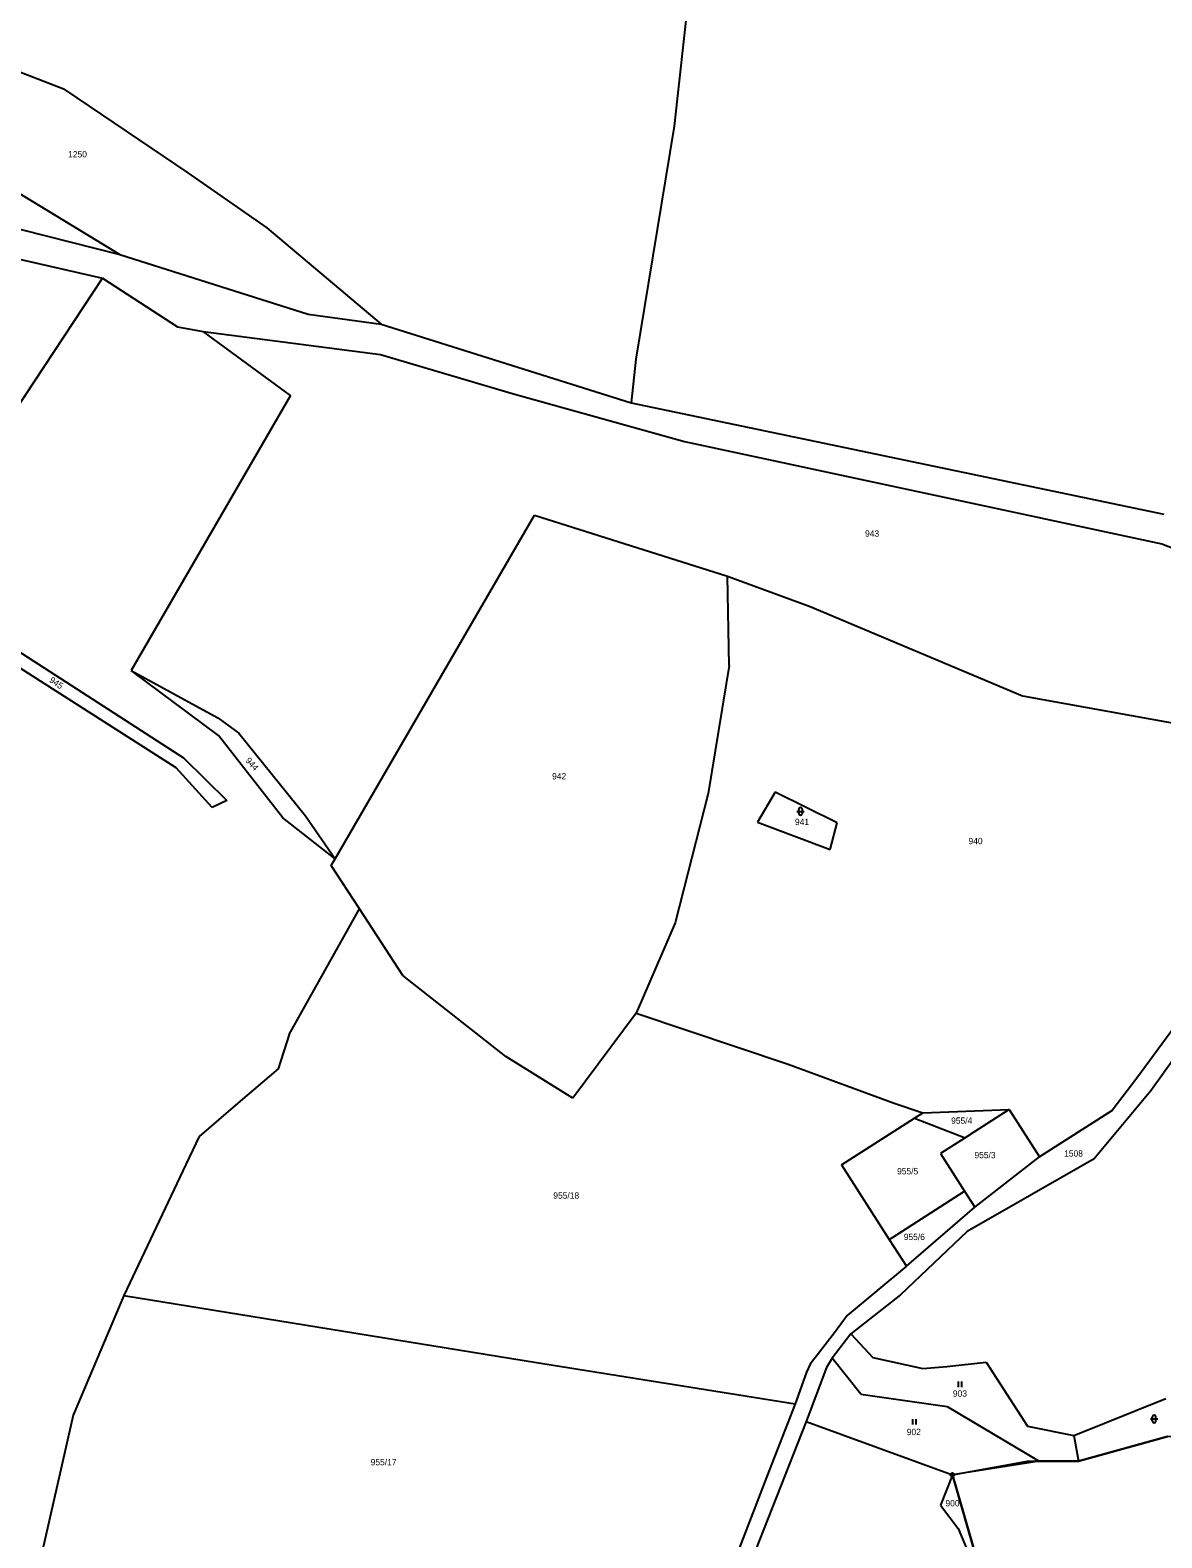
# Model space of a CAD drawing. Extents: x -760642 to -757221, y -1092371 to -1088855.
# Drawn here: x -759517.9 to -759213, y -1091814.5 to -1091408.1 of the extents above; entities that cross this region are included whole.
import ezdxf

# ---------------------------------------------------------------- set-up
doc = ezdxf.new("R2010")
doc.units = 0
for name, color, linetype in [('Vrstva 1', 7, 'Continuous'), ('Vrstva 13', 7, 'Continuous'), ('Vrstva 18', 7, 'Continuous'), ('Vrstva 24', 7, 'Continuous'), ('Vrstva 25', 7, 'Continuous'), ('Vrstva 28', 7, 'Continuous')]:
    doc.layers.add(name, color=color, linetype=linetype)

msp = doc.modelspace()

# ---------------------------------------------------------------- linework, layer by layer
at = {"layer": 'Vrstva 1'}
for p, q in [((-759336.04, -1091359.28), (-759344.44, -1091433.97)), ((-759508.63, -1091424.1), (-759544.7, -1091410.36)), ((-759508.63, -1091424.1), (-759475.4, -1091446.57)), ((-759344.44, -1091433.97), (-759354.76, -1091496.83)), ((-759589.77, -1091444.33), (-759493.77, -1091468.61)), ((-759475.4, -1091446.57), (-759454.15, -1091461.4)), ((-759592.93, -1091453.44), (-759498.45, -1091474.93)), ((-759524, -1091450.19), (-759493.77, -1091468.61)), ((-759454.15, -1091461.4), (-759423.37, -1091487.35)), ((-759493.77, -1091468.61), (-759442.97, -1091484.64)), ((-759551.73, -1091555.78), (-759498.45, -1091474.93)), ((-759498.45, -1091474.93), (-759478.22, -1091488.09)), ((-759442.97, -1091484.64), (-759423.37, -1091487.35)), ((-759478.22, -1091488.09), (-759471.32, -1091489.38)), ((-759447.73, -1091506.59), (-759471.32, -1091489.38)), ((-759471.32, -1091489.38), (-759423.5, -1091495.58)), ((-759423.37, -1091487.35), (-759355.96, -1091508.53)), ((-759423.5, -1091495.58), (-759387.72, -1091506.19)), ((-759354.76, -1091496.83), (-759355.96, -1091508.53)), ((-759387.72, -1091506.19), (-759341.65, -1091518.97)), ((-759447.73, -1091506.59), (-759490.74, -1091580.74)), ((-759355.96, -1091508.53), (-759212.45, -1091538.54)), ((-759341.65, -1091518.97), (-759213.03, -1091546.61)), ((-759435.76, -1091631.5), (-759382, -1091538.82)), ((-759382, -1091538.82), (-759329.99, -1091555.26)), ((-759213.03, -1091546.61), (-759176.04, -1091560.8)), ((-759478.53, -1091606.93), (-759553.56, -1091559.12)), ((-759551.73, -1091555.78), (-759476.57, -1091604.24)), ((-759329.99, -1091555.26), (-759307.72, -1091563.44)), ((-759329.59, -1091579.38), (-759329.99, -1091555.26)), ((-759307.72, -1091563.44), (-759250.54, -1091587.55)), ((-759329.59, -1091579.38), (-759335.2, -1091613.85)), ((-759490.74, -1091580.74), (-759467.33, -1091593.5)), ((-759467.2, -1091598.21), (-759490.74, -1091580.74)), ((-759250.54, -1091587.55), (-759179.64, -1091600.4)), ((-759467.33, -1091593.5), (-759461.7, -1091597.57)), ((-759449.86, -1091620.44), (-759467.2, -1091598.21)), ((-759461.7, -1091597.57), (-759443.7, -1091619.91)), ((-759468.87, -1091617.59), (-759478.53, -1091606.93)), ((-759476.57, -1091604.24), (-759464.95, -1091615.75)), ((-759464.95, -1091615.75), (-759468.87, -1091617.59)), ((-759335.2, -1091613.85), (-759344.14, -1091648.72)), ((-759317.15, -1091613.52), (-759321.95, -1091621.6)), ((-759300.48, -1091621.77), (-759317.15, -1091613.52)), ((-759443.7, -1091619.91), (-759435.76, -1091631.5)), ((-759435.76, -1091631.5), (-759449.86, -1091620.44)), ((-759321.95, -1091621.6), (-759302.38, -1091628.99)), ((-759302.38, -1091628.99), (-759300.48, -1091621.77)), ((-759436.78, -1091633.3), (-759435.76, -1091631.5)), ((-759429.17, -1091644.97), (-759436.78, -1091633.3)), ((-759448.14, -1091678.83), (-759429.17, -1091644.97)), ((-759417.48, -1091662.9), (-759429.17, -1091644.97)), ((-759344.14, -1091648.72), (-759354.67, -1091673.09)), ((-759389.74, -1091684.73), (-759417.48, -1091662.9)), ((-759204.99, -1091670.57), (-759219.73, -1091690.6)), ((-759354.67, -1091673.09), (-759371.69, -1091695.95)), ((-759354.67, -1091673.09), (-759313.71, -1091686.85)), ((-759448.14, -1091678.83), (-759451.13, -1091688.07)), ((-759206.15, -1091680.38), (-759216.01, -1091694.01)), ((-759371.69, -1091695.95), (-759389.74, -1091684.73)), ((-759451.13, -1091688.07), (-759461.95, -1091697.33)), ((-759313.71, -1091686.85), (-759285.1, -1091697.29)), ((-759219.73, -1091690.6), (-759226.39, -1091699.26)), ((-759461.95, -1091697.33), (-759472.38, -1091706.27)), ((-759285.1, -1091697.29), (-759277.42, -1091699.95)), ((-759216.01, -1091694.01), (-759231.27, -1091712.36)), ((-759299.31, -1091713.98), (-759279.61, -1091701.35)), ((-759279.61, -1091701.35), (-759277.42, -1091699.95)), ((-759279.61, -1091701.35), (-759266.03, -1091706.67)), ((-759277.42, -1091699.95), (-759254.11, -1091699.03)), ((-759254.11, -1091699.03), (-759263.62, -1091705.12)), ((-759254.11, -1091699.03), (-759245.95, -1091711.75)), ((-759226.39, -1091699.26), (-759245.95, -1091711.75)), ((-759263.62, -1091705.12), (-759266.03, -1091706.67)), ((-759472.38, -1091706.27), (-759475.95, -1091713.82)), ((-759266.03, -1091706.67), (-759272.63, -1091710.91)), ((-759272.63, -1091710.91), (-759266.13, -1091721.03)), ((-759231.27, -1091712.36), (-759265.46, -1091731.92)), ((-759263.36, -1091725.35), (-759245.95, -1091711.75)), ((-759475.95, -1091713.82), (-759492.66, -1091749.12)), ((-759299.31, -1091713.98), (-759286.43, -1091734.06)), ((-759285.59, -1091733.52), (-759266.13, -1091721.03)), ((-759266.13, -1091721.03), (-759263.36, -1091725.35)), ((-759281.79, -1091741.29), (-759263.36, -1091725.35)), ((-759286.43, -1091734.06), (-759285.59, -1091733.52)), ((-759265.46, -1091731.92), (-759283.42, -1091748.95)), ((-759286.43, -1091734.06), (-759281.79, -1091741.29)), ((-759281.79, -1091741.29), (-759297.82, -1091754.55)), ((-759492.66, -1091749.12), (-759506.33, -1091781.42)), ((-759492.66, -1091749.12), (-759381.5, -1091767.24)), ((-759283.42, -1091748.95), (-759296.81, -1091759.47)), ((-759297.82, -1091754.55), (-759301.24, -1091759.22)), ((-759301.24, -1091759.22), (-759307.76, -1091767.62)), ((-759296.81, -1091759.47), (-759301.82, -1091766.04)), ((-759296.81, -1091759.47), (-759290.89, -1091765.88)), ((-759301.82, -1091766.04), (-759303.38, -1091768.52)), ((-759294.11, -1091775.77), (-759301.82, -1091766.04)), ((-759290.89, -1091765.88), (-759277.42, -1091768.79)), ((-759381.5, -1091767.24), (-759311.76, -1091778.34)), ((-759308.71, -1091769.84), (-759311.76, -1091778.34)), ((-759303.38, -1091768.52), (-759308.81, -1091783.1)), ((-759307.76, -1091767.62), (-759308.71, -1091769.84)), ((-759277.42, -1091768.79), (-759270.93, -1091768.25)), ((-759270.93, -1091768.25), (-759260.34, -1091767.08)), ((-759260.34, -1091767.08), (-759249.22, -1091784.33)), ((-759311.76, -1091778.34), (-759319.4, -1091797.96)), ((-759294.11, -1091775.77), (-759270.87, -1091779.03)), ((-759236.72, -1091786.9), (-759211.96, -1091776.89)), ((-759506.33, -1091781.42), (-759516.69, -1091827.12)), ((-759270.87, -1091779.03), (-759246.02, -1091793.76)), ((-759308.81, -1091783.1), (-759329.95, -1091836.56)), ((-759308.81, -1091783.1), (-759269.45, -1091797.46)), ((-759249.22, -1091784.33), (-759236.72, -1091786.9)), ((-759236.72, -1091786.9), (-759235.47, -1091793.76)), ((-759319.4, -1091797.96), (-759326.8, -1091817.03)), ((-759269.45, -1091797.46), (-759272.64, -1091805.66)), ((-759272.64, -1091805.66), (-759267.86, -1091811.91)), ((-759267.86, -1091811.91), (-759259.52, -1091831.81))]:
    msp.add_line(p, q, dxfattribs=at)
at = {"layer": 'Vrstva 13'}
for p, q in [((-759235.47, -1091793.76), (-759211.44, -1091787.19)), ((-759269.45, -1091797.46), (-759249.22, -1091793.76)), ((-759249.22, -1091793.76), (-759246.02, -1091793.76)), ((-759246.02, -1091793.76), (-759235.47, -1091793.76)), ((-759259.52, -1091831.81), (-759269.45, -1091797.46))]:
    msp.add_line(p, q, dxfattribs=at)
at = {"layer": 'Vrstva 24'}
for radius in [0.5, 0.0327]:
    msp.add_circle((-759269.45, -1091797.46), radius, dxfattribs=at)
at = {"layer": 'Vrstva 25'}
for p, q in [((-759311.33, -1091618.67), (-759309.33, -1091618.67)), ((-759310.83, -1091619.17), (-759310.83, -1091618.17)), ((-759309.83, -1091619.17), (-759309.83, -1091618.17)), ((-759267.897, -1091772.345), (-759267.897, -1091773.845)), ((-759266.875, -1091773.845), (-759266.875, -1091772.345)), ((-759280.217, -1091782.465), (-759280.217, -1091783.965)), ((-759279.195, -1091783.965), (-759279.195, -1091782.465)), ((-759216.09, -1091782.43), (-759214.09, -1091782.43)), ((-759215.59, -1091782.93), (-759215.59, -1091781.93)), ((-759214.59, -1091782.93), (-759214.59, -1091781.93))]:
    msp.add_line(p, q, dxfattribs=at)
for centre, start, end in [((-759310.33, -1091618.17), 0, 180), ((-759310.33, -1091619.17), 180, 0), ((-759215.09, -1091781.93), 0, 180), ((-759215.09, -1091782.93), 180, 0)]:
    msp.add_arc(centre, 0.5, start, end, dxfattribs=at)
at = {"layer": 'Vrstva 28'}
msp.add_lwpolyline([(-758854.73, -1091748.51), (-758927.37, -1091748.94), (-758951.68, -1091748.9), (-758986.11, -1091749.03), (-759010.94, -1091749.41), (-759024.12, -1091751.33), (-759029.27, -1091753.3), (-759059.56, -1091764.89), (-759085.17, -1091780.09), (-759093.14, -1091783.66), (-759104.81, -1091788.91), (-759125.32, -1091795.01), (-759137.1, -1091793.11), (-759161.94, -1091789.1), (-759172.28, -1091787.43), (-759211.44, -1091787.19), (-759235.47, -1091793.76), (-759246.02, -1091793.76), (-759269.45, -1091797.46), (-759259.52, -1091831.81)], dxfattribs=at)

# ---------------------------------------------------------------- texts
at = {"layer": 'Vrstva 18'}
for s, p in [('1250', (-759507.67, -1091442.43)), ('943', (-759292.97, -1091544.65)), ('942', (-759377.29, -1091610.07)), ('941', (-759311.85, -1091622.37)), ('940', (-759265.09, -1091627.52)), ('955/4', (-759269.77, -1091702.88)), ('955/3', (-759263.49, -1091712.16)), ('1508', (-759239.328, -1091711.72)), ('955/5', (-759284.33, -1091716.52)), ('955/18', (-759376.96, -1091723.07)), ('955/6', (-759282.53, -1091734.22)), ('903', (-759269.3, -1091776.42)), ('902', (-759281.73, -1091786.78)), ('955/17', (-759426.16, -1091794.94)), ('900', (-759271.302, -1091805.99))]:
    msp.add_text(s, height=1.7, dxfattribs=at).set_placement(p)
for s, rotation, p in [('945', 325.27656, (-759512.89, -1091583.67)), ('944', 312.2118, (-759460.03, -1091605.09))]:
    msp.add_text(s, height=1.7, rotation=rotation, dxfattribs=at).set_placement(p)

doc.saveas('drawing.dxf')
